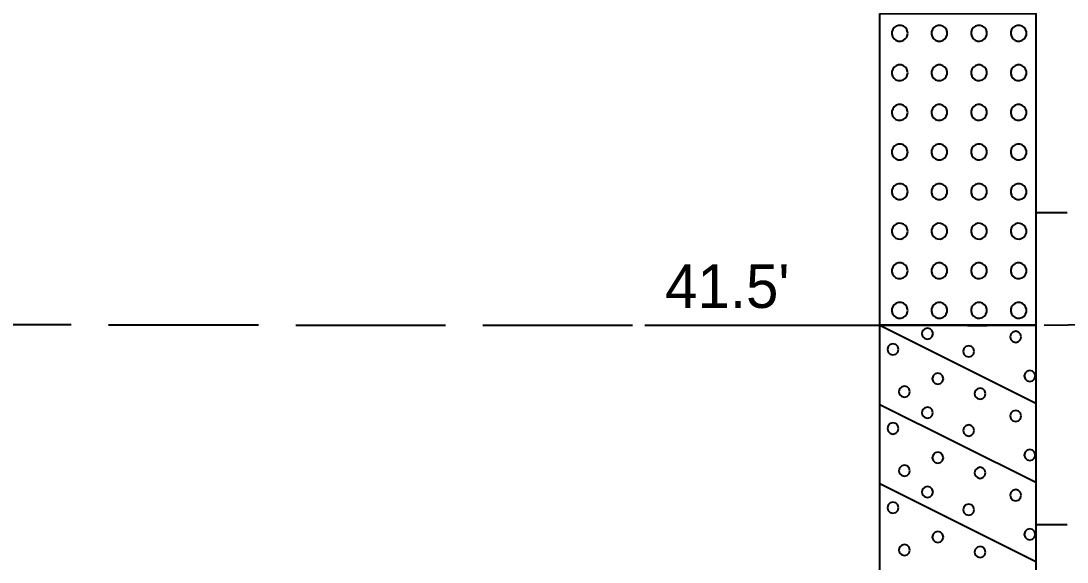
# Model space of a CAD drawing. Extents: x -582 to 653, y -817 to -3.
# Drawn here: x -81.59 to -64.82, y -739.22 to -730.54 of the extents above; entities that cross this region are included whole.
import ezdxf

# ---------------------------------------------------------------- set-up
doc = ezdxf.new("R2010")
doc.units = 0
doc.header["$LTSCALE"] = 0.4
doc.linetypes.add('LONG_DASHED', pattern=[7.5, 6, -1.5])
doc.layers.add('26', color=7, linetype='LONG_DASHED', lineweight=40)
doc.layers.add('27', color=7, linetype='Continuous', lineweight=40)

msp = doc.modelspace()

# ---------------------------------------------------------------- linework, layer by layer
at = {"layer": '26'}
msp.add_spline([(-89.1835, -735.3917), (-71.5863, -735.4226), (-67.8189, -735.4226), (-65.3189, -735.4226), (-45.0863, -734.6526), (-41.3189, -734.6526), (-38.8189, -734.6526), (-12.827, -734.6889)], degree=3, dxfattribs=at)
at = {"layer": '27'}
for p, q in [((-64.8189, -733.6226), (-65.3189, -733.6226)), ((-71.5863, -735.4226), (-67.8189, -735.4226)), ((-67.8189, -735.4226), (-65.3189, -736.6726)), ((-67.8189, -736.6926), (-65.3189, -737.9426)), ((-67.8189, -737.9626), (-65.3189, -739.2126)), ((-64.8189, -738.6226), (-65.3189, -738.6226))]:
    msp.add_line(p, q, dxfattribs=at)
for points in [[(-67.8189, -730.4226), (-65.3189, -730.4226), (-65.3189, -735.4226), (-67.8189, -735.4226)], [(-67.3743, -730.7401), (-67.3758, -730.7204), (-67.388, -730.6827), (-67.4111, -730.6506), (-67.443, -730.6272), (-67.4805, -730.6147), (-67.5201, -730.6144), (-67.5578, -730.6262), (-67.5901, -730.6491), (-67.6138, -730.6808), (-67.6266, -730.7182), (-67.6273, -730.7577), (-67.6158, -730.7956), (-67.5932, -730.8281), (-67.5618, -730.852), (-67.5245, -730.8652), (-67.4849, -730.8662), (-67.447, -730.855), (-67.4143, -730.8327), (-67.39, -730.8015), (-67.3766, -730.7643)], [(-66.7393, -730.7401), (-66.7408, -730.7204), (-66.753, -730.6827), (-66.7761, -730.6506), (-66.808, -730.6272), (-66.8455, -730.6147), (-66.8851, -730.6144), (-66.9228, -730.6262), (-66.9551, -730.6491), (-66.9788, -730.6808), (-66.9916, -730.7182), (-66.9923, -730.7577), (-66.9808, -730.7956), (-66.9582, -730.8281), (-66.9268, -730.852), (-66.8895, -730.8652), (-66.8499, -730.8662), (-66.812, -730.855), (-66.7793, -730.8327), (-66.755, -730.8015), (-66.7416, -730.7643)], [(-66.1043, -730.7401), (-66.1058, -730.7204), (-66.118, -730.6827), (-66.1411, -730.6506), (-66.173, -730.6272), (-66.2105, -730.6147), (-66.2501, -730.6144), (-66.2878, -730.6262), (-66.3201, -730.6491), (-66.3438, -730.6808), (-66.3566, -730.7182), (-66.3573, -730.7577), (-66.3458, -730.7956), (-66.3232, -730.8281), (-66.2918, -730.852), (-66.2545, -730.8652), (-66.2149, -730.8662), (-66.177, -730.855), (-66.1443, -730.8327), (-66.12, -730.8015), (-66.1066, -730.7643)], [(-65.4693, -730.7401), (-65.4708, -730.7204), (-65.483, -730.6827), (-65.5061, -730.6506), (-65.538, -730.6272), (-65.5755, -730.6147), (-65.6151, -730.6144), (-65.6528, -730.6262), (-65.6851, -730.6491), (-65.7088, -730.6808), (-65.7216, -730.7182), (-65.7223, -730.7577), (-65.7108, -730.7956), (-65.6882, -730.8281), (-65.6568, -730.852), (-65.6195, -730.8652), (-65.5799, -730.8662), (-65.542, -730.855), (-65.5093, -730.8327), (-65.485, -730.8015), (-65.4716, -730.7643)], [(-67.3743, -731.3751), (-67.3758, -731.3554), (-67.388, -731.3177), (-67.4111, -731.2856), (-67.443, -731.2622), (-67.4805, -731.2497), (-67.5201, -731.2494), (-67.5578, -731.2612), (-67.5901, -731.2841), (-67.6138, -731.3158), (-67.6266, -731.3532), (-67.6273, -731.3927), (-67.6158, -731.4306), (-67.5932, -731.4631), (-67.5618, -731.487), (-67.5245, -731.5002), (-67.4849, -731.5012), (-67.447, -731.49), (-67.4143, -731.4677), (-67.39, -731.4365), (-67.3766, -731.3993)], [(-66.7393, -731.3751), (-66.7408, -731.3554), (-66.753, -731.3177), (-66.7761, -731.2856), (-66.808, -731.2622), (-66.8455, -731.2497), (-66.8851, -731.2494), (-66.9228, -731.2612), (-66.9551, -731.2841), (-66.9788, -731.3158), (-66.9916, -731.3532), (-66.9923, -731.3927), (-66.9808, -731.4306), (-66.9582, -731.4631), (-66.9268, -731.487), (-66.8895, -731.5002), (-66.8499, -731.5012), (-66.812, -731.49), (-66.7793, -731.4677), (-66.755, -731.4365), (-66.7416, -731.3993)], [(-66.1043, -731.3751), (-66.1058, -731.3554), (-66.118, -731.3177), (-66.1411, -731.2856), (-66.173, -731.2622), (-66.2105, -731.2497), (-66.2501, -731.2494), (-66.2878, -731.2612), (-66.3201, -731.2841), (-66.3438, -731.3158), (-66.3566, -731.3532), (-66.3573, -731.3927), (-66.3458, -731.4306), (-66.3232, -731.4631), (-66.2918, -731.487), (-66.2545, -731.5002), (-66.2149, -731.5012), (-66.177, -731.49), (-66.1443, -731.4677), (-66.12, -731.4365), (-66.1066, -731.3993)], [(-65.4693, -731.3751), (-65.4708, -731.3554), (-65.483, -731.3177), (-65.5061, -731.2856), (-65.538, -731.2622), (-65.5755, -731.2497), (-65.6151, -731.2494), (-65.6528, -731.2612), (-65.6851, -731.2841), (-65.7088, -731.3158), (-65.7216, -731.3532), (-65.7223, -731.3927), (-65.7108, -731.4306), (-65.6882, -731.4631), (-65.6568, -731.487), (-65.6195, -731.5002), (-65.5799, -731.5012), (-65.542, -731.49), (-65.5093, -731.4677), (-65.485, -731.4365), (-65.4716, -731.3993)], [(-67.3743, -732.0101), (-67.3758, -731.9904), (-67.388, -731.9527), (-67.4111, -731.9206), (-67.443, -731.8972), (-67.4805, -731.8847), (-67.5201, -731.8844), (-67.5578, -731.8962), (-67.5901, -731.9191), (-67.6138, -731.9508), (-67.6266, -731.9882), (-67.6273, -732.0277), (-67.6158, -732.0656), (-67.5932, -732.0981), (-67.5618, -732.122), (-67.5245, -732.1352), (-67.4849, -732.1362), (-67.447, -732.125), (-67.4143, -732.1027), (-67.39, -732.0715), (-67.3766, -732.0343)], [(-66.7393, -732.0101), (-66.7408, -731.9904), (-66.753, -731.9527), (-66.7761, -731.9206), (-66.808, -731.8972), (-66.8455, -731.8847), (-66.8851, -731.8844), (-66.9228, -731.8962), (-66.9551, -731.9191), (-66.9788, -731.9508), (-66.9916, -731.9882), (-66.9923, -732.0277), (-66.9808, -732.0656), (-66.9582, -732.0981), (-66.9268, -732.122), (-66.8895, -732.1352), (-66.8499, -732.1362), (-66.812, -732.125), (-66.7793, -732.1027), (-66.755, -732.0715), (-66.7416, -732.0343)], [(-66.1043, -732.0101), (-66.1058, -731.9904), (-66.118, -731.9527), (-66.1411, -731.9206), (-66.173, -731.8972), (-66.2105, -731.8847), (-66.2501, -731.8844), (-66.2878, -731.8962), (-66.3201, -731.9191), (-66.3438, -731.9508), (-66.3566, -731.9882), (-66.3573, -732.0277), (-66.3458, -732.0656), (-66.3232, -732.0981), (-66.2918, -732.122), (-66.2545, -732.1352), (-66.2149, -732.1362), (-66.177, -732.125), (-66.1443, -732.1027), (-66.12, -732.0715), (-66.1066, -732.0343)], [(-65.4693, -732.0101), (-65.4708, -731.9904), (-65.483, -731.9527), (-65.5061, -731.9206), (-65.538, -731.8972), (-65.5755, -731.8847), (-65.6151, -731.8844), (-65.6528, -731.8962), (-65.6851, -731.9191), (-65.7088, -731.9508), (-65.7216, -731.9882), (-65.7223, -732.0277), (-65.7108, -732.0656), (-65.6882, -732.0981), (-65.6568, -732.122), (-65.6195, -732.1352), (-65.5799, -732.1362), (-65.542, -732.125), (-65.5093, -732.1027), (-65.485, -732.0715), (-65.4716, -732.0343)], [(-67.3743, -732.6451), (-67.3758, -732.6254), (-67.388, -732.5877), (-67.4111, -732.5556), (-67.443, -732.5322), (-67.4805, -732.5197), (-67.5201, -732.5194), (-67.5578, -732.5312), (-67.5901, -732.5541), (-67.6138, -732.5858), (-67.6266, -732.6232), (-67.6273, -732.6627), (-67.6158, -732.7006), (-67.5932, -732.7331), (-67.5618, -732.757), (-67.5245, -732.7702), (-67.4849, -732.7712), (-67.447, -732.76), (-67.4143, -732.7377), (-67.39, -732.7065), (-67.3766, -732.6693)], [(-66.7393, -732.6451), (-66.7408, -732.6254), (-66.753, -732.5877), (-66.7761, -732.5556), (-66.808, -732.5322), (-66.8455, -732.5197), (-66.8851, -732.5194), (-66.9228, -732.5312), (-66.9551, -732.5541), (-66.9788, -732.5858), (-66.9916, -732.6232), (-66.9923, -732.6627), (-66.9808, -732.7006), (-66.9582, -732.7331), (-66.9268, -732.757), (-66.8895, -732.7702), (-66.8499, -732.7712), (-66.812, -732.76), (-66.7793, -732.7377), (-66.755, -732.7065), (-66.7416, -732.6693)], [(-66.1043, -732.6451), (-66.1058, -732.6254), (-66.118, -732.5877), (-66.1411, -732.5556), (-66.173, -732.5322), (-66.2105, -732.5197), (-66.2501, -732.5194), (-66.2878, -732.5312), (-66.3201, -732.5541), (-66.3438, -732.5858), (-66.3566, -732.6232), (-66.3573, -732.6627), (-66.3458, -732.7006), (-66.3232, -732.7331), (-66.2918, -732.757), (-66.2545, -732.7702), (-66.2149, -732.7712), (-66.177, -732.76), (-66.1443, -732.7377), (-66.12, -732.7065), (-66.1066, -732.6693)], [(-65.4693, -732.6451), (-65.4708, -732.6254), (-65.483, -732.5877), (-65.5061, -732.5556), (-65.538, -732.5322), (-65.5755, -732.5197), (-65.6151, -732.5194), (-65.6528, -732.5312), (-65.6851, -732.5541), (-65.7088, -732.5858), (-65.7216, -732.6232), (-65.7223, -732.6627), (-65.7108, -732.7006), (-65.6882, -732.7331), (-65.6568, -732.757), (-65.6195, -732.7702), (-65.5799, -732.7712), (-65.542, -732.76), (-65.5093, -732.7377), (-65.485, -732.7065), (-65.4716, -732.6693)], [(-67.3743, -733.2801), (-67.3758, -733.2604), (-67.388, -733.2227), (-67.4111, -733.1906), (-67.443, -733.1672), (-67.4805, -733.1547), (-67.5201, -733.1544), (-67.5578, -733.1662), (-67.5901, -733.1891), (-67.6138, -733.2208), (-67.6266, -733.2582), (-67.6273, -733.2977), (-67.6158, -733.3356), (-67.5932, -733.3681), (-67.5618, -733.392), (-67.5245, -733.4052), (-67.4849, -733.4062), (-67.447, -733.395), (-67.4143, -733.3727), (-67.39, -733.3415), (-67.3766, -733.3043)], [(-66.7393, -733.2801), (-66.7408, -733.2604), (-66.753, -733.2227), (-66.7761, -733.1906), (-66.808, -733.1672), (-66.8455, -733.1547), (-66.8851, -733.1544), (-66.9228, -733.1662), (-66.9551, -733.1891), (-66.9788, -733.2208), (-66.9916, -733.2582), (-66.9923, -733.2977), (-66.9808, -733.3356), (-66.9582, -733.3681), (-66.9268, -733.392), (-66.8895, -733.4052), (-66.8499, -733.4062), (-66.812, -733.395), (-66.7793, -733.3727), (-66.755, -733.3415), (-66.7416, -733.3043)], [(-66.1043, -733.2801), (-66.1058, -733.2604), (-66.118, -733.2227), (-66.1411, -733.1906), (-66.173, -733.1672), (-66.2105, -733.1547), (-66.2501, -733.1544), (-66.2878, -733.1662), (-66.3201, -733.1891), (-66.3438, -733.2208), (-66.3566, -733.2582), (-66.3573, -733.2977), (-66.3458, -733.3356), (-66.3232, -733.3681), (-66.2918, -733.392), (-66.2545, -733.4052), (-66.2149, -733.4062), (-66.177, -733.395), (-66.1443, -733.3727), (-66.12, -733.3415), (-66.1066, -733.3043)], [(-65.4693, -733.2801), (-65.4708, -733.2604), (-65.483, -733.2227), (-65.5061, -733.1906), (-65.538, -733.1672), (-65.5755, -733.1547), (-65.6151, -733.1544), (-65.6528, -733.1662), (-65.6851, -733.1891), (-65.7088, -733.2208), (-65.7216, -733.2582), (-65.7223, -733.2977), (-65.7108, -733.3356), (-65.6882, -733.3681), (-65.6568, -733.392), (-65.6195, -733.4052), (-65.5799, -733.4062), (-65.542, -733.395), (-65.5093, -733.3727), (-65.485, -733.3415), (-65.4716, -733.3043)], [(-67.3743, -733.9151), (-67.3758, -733.8954), (-67.388, -733.8577), (-67.4111, -733.8256), (-67.443, -733.8022), (-67.4805, -733.7897), (-67.5201, -733.7894), (-67.5578, -733.8012), (-67.5901, -733.8241), (-67.6138, -733.8558), (-67.6266, -733.8932), (-67.6273, -733.9327), (-67.6158, -733.9706), (-67.5932, -734.0031), (-67.5618, -734.027), (-67.5245, -734.0402), (-67.4849, -734.0412), (-67.447, -734.03), (-67.4143, -734.0077), (-67.39, -733.9765), (-67.3766, -733.9393)], [(-66.7393, -733.9151), (-66.7408, -733.8954), (-66.753, -733.8577), (-66.7761, -733.8256), (-66.808, -733.8022), (-66.8455, -733.7897), (-66.8851, -733.7894), (-66.9228, -733.8012), (-66.9551, -733.8241), (-66.9788, -733.8558), (-66.9916, -733.8932), (-66.9923, -733.9327), (-66.9808, -733.9706), (-66.9582, -734.0031), (-66.9268, -734.027), (-66.8895, -734.0402), (-66.8499, -734.0412), (-66.812, -734.03), (-66.7793, -734.0077), (-66.755, -733.9765), (-66.7416, -733.9393)], [(-66.1043, -733.9151), (-66.1058, -733.8954), (-66.118, -733.8577), (-66.1411, -733.8256), (-66.173, -733.8022), (-66.2105, -733.7897), (-66.2501, -733.7894), (-66.2878, -733.8012), (-66.3201, -733.8241), (-66.3438, -733.8558), (-66.3566, -733.8932), (-66.3573, -733.9327), (-66.3458, -733.9706), (-66.3232, -734.0031), (-66.2918, -734.027), (-66.2545, -734.0402), (-66.2149, -734.0412), (-66.177, -734.03), (-66.1443, -734.0077), (-66.12, -733.9765), (-66.1066, -733.9393)], [(-65.4693, -733.9151), (-65.4708, -733.8954), (-65.483, -733.8577), (-65.5061, -733.8256), (-65.538, -733.8022), (-65.5755, -733.7897), (-65.6151, -733.7894), (-65.6528, -733.8012), (-65.6851, -733.8241), (-65.7088, -733.8558), (-65.7216, -733.8932), (-65.7223, -733.9327), (-65.7108, -733.9706), (-65.6882, -734.0031), (-65.6568, -734.027), (-65.6195, -734.0402), (-65.5799, -734.0412), (-65.542, -734.03), (-65.5093, -734.0077), (-65.485, -733.9765), (-65.4716, -733.9393)], [(-67.3743, -734.5501), (-67.3758, -734.5304), (-67.388, -734.4927), (-67.4111, -734.4606), (-67.443, -734.4372), (-67.4805, -734.4247), (-67.5201, -734.4244), (-67.5578, -734.4362), (-67.5901, -734.4591), (-67.6138, -734.4908), (-67.6266, -734.5282), (-67.6273, -734.5677), (-67.6158, -734.6056), (-67.5932, -734.6381), (-67.5618, -734.662), (-67.5245, -734.6752), (-67.4849, -734.6762), (-67.447, -734.665), (-67.4143, -734.6427), (-67.39, -734.6115), (-67.3766, -734.5743)], [(-66.7393, -734.5501), (-66.7408, -734.5304), (-66.753, -734.4927), (-66.7761, -734.4606), (-66.808, -734.4372), (-66.8455, -734.4247), (-66.8851, -734.4244), (-66.9228, -734.4362), (-66.9551, -734.4591), (-66.9788, -734.4908), (-66.9916, -734.5282), (-66.9923, -734.5677), (-66.9808, -734.6056), (-66.9582, -734.6381), (-66.9268, -734.662), (-66.8895, -734.6752), (-66.8499, -734.6762), (-66.812, -734.665), (-66.7793, -734.6427), (-66.755, -734.6115), (-66.7416, -734.5743)], [(-66.1043, -734.5501), (-66.1058, -734.5304), (-66.118, -734.4927), (-66.1411, -734.4606), (-66.173, -734.4372), (-66.2105, -734.4247), (-66.2501, -734.4244), (-66.2878, -734.4362), (-66.3201, -734.4591), (-66.3438, -734.4908), (-66.3566, -734.5282), (-66.3573, -734.5677), (-66.3458, -734.6056), (-66.3232, -734.6381), (-66.2918, -734.662), (-66.2545, -734.6752), (-66.2149, -734.6762), (-66.177, -734.665), (-66.1443, -734.6427), (-66.12, -734.6115), (-66.1066, -734.5743)], [(-65.4693, -734.5501), (-65.4708, -734.5304), (-65.483, -734.4927), (-65.5061, -734.4606), (-65.538, -734.4372), (-65.5755, -734.4247), (-65.6151, -734.4244), (-65.6528, -734.4362), (-65.6851, -734.4591), (-65.7088, -734.4908), (-65.7216, -734.5282), (-65.7223, -734.5677), (-65.7108, -734.6056), (-65.6882, -734.6381), (-65.6568, -734.662), (-65.6195, -734.6752), (-65.5799, -734.6762), (-65.542, -734.665), (-65.5093, -734.6427), (-65.485, -734.6115), (-65.4716, -734.5743)], [(-67.3743, -735.1851), (-67.3758, -735.1654), (-67.388, -735.1277), (-67.4111, -735.0956), (-67.443, -735.0722), (-67.4805, -735.0597), (-67.5201, -735.0594), (-67.5578, -735.0712), (-67.5901, -735.0941), (-67.6138, -735.1258), (-67.6266, -735.1632), (-67.6273, -735.2027), (-67.6158, -735.2406), (-67.5932, -735.2731), (-67.5618, -735.297), (-67.5245, -735.3102), (-67.4849, -735.3112), (-67.447, -735.3), (-67.4143, -735.2777), (-67.39, -735.2465), (-67.3766, -735.2093)], [(-66.7393, -735.1851), (-66.7408, -735.1654), (-66.753, -735.1277), (-66.7761, -735.0956), (-66.808, -735.0722), (-66.8455, -735.0597), (-66.8851, -735.0594), (-66.9228, -735.0712), (-66.9551, -735.0941), (-66.9788, -735.1258), (-66.9916, -735.1632), (-66.9923, -735.2027), (-66.9808, -735.2406), (-66.9582, -735.2731), (-66.9268, -735.297), (-66.8895, -735.3102), (-66.8499, -735.3112), (-66.812, -735.3), (-66.7793, -735.2777), (-66.755, -735.2465), (-66.7416, -735.2093)], [(-66.1043, -735.1851), (-66.1058, -735.1654), (-66.118, -735.1277), (-66.1411, -735.0956), (-66.173, -735.0722), (-66.2105, -735.0597), (-66.2501, -735.0594), (-66.2878, -735.0712), (-66.3201, -735.0941), (-66.3438, -735.1258), (-66.3566, -735.1632), (-66.3573, -735.2027), (-66.3458, -735.2406), (-66.3232, -735.2731), (-66.2918, -735.297), (-66.2545, -735.3102), (-66.2149, -735.3112), (-66.177, -735.3), (-66.1443, -735.2777), (-66.12, -735.2465), (-66.1066, -735.2093)], [(-65.4693, -735.1851), (-65.4708, -735.1654), (-65.483, -735.1277), (-65.5061, -735.0956), (-65.538, -735.0722), (-65.5755, -735.0597), (-65.6151, -735.0594), (-65.6528, -735.0712), (-65.6851, -735.0941), (-65.7088, -735.1258), (-65.7216, -735.1632), (-65.7223, -735.2027), (-65.7108, -735.2406), (-65.6882, -735.2731), (-65.6568, -735.297), (-65.6195, -735.3102), (-65.5799, -735.3112), (-65.542, -735.3), (-65.5093, -735.2777), (-65.485, -735.2465), (-65.4716, -735.2093)], [(-67.8189, -735.4226), (-65.3189, -735.4226), (-65.3189, -740.4226), (-67.8189, -740.4226)], [(-66.9682, -735.5589), (-66.9801, -735.5145), (-67.0126, -735.482), (-67.0571, -735.47), (-67.1015, -735.482), (-67.1341, -735.5145), (-67.146, -735.5589), (-67.1341, -735.6034), (-67.1015, -735.6359), (-67.0571, -735.6478), (-67.0126, -735.6359), (-66.9801, -735.6034)], [(-65.5534, -735.6099), (-65.5653, -735.5654), (-65.5978, -735.5329), (-65.6423, -735.521), (-65.6867, -735.5329), (-65.7192, -735.5654), (-65.7312, -735.6099), (-65.7192, -735.6543), (-65.6867, -735.6869), (-65.6423, -735.6988), (-65.5978, -735.6869), (-65.5653, -735.6543)], [(-67.5213, -735.8107), (-67.5332, -735.7663), (-67.5657, -735.7337), (-67.6102, -735.7218), (-67.6546, -735.7337), (-67.6872, -735.7663), (-67.6991, -735.8107), (-67.6872, -735.8552), (-67.6546, -735.8877), (-67.6102, -735.8996), (-67.5657, -735.8877), (-67.5332, -735.8552)], [(-66.3059, -735.8438), (-66.3179, -735.7993), (-66.3504, -735.7668), (-66.3948, -735.7549), (-66.4393, -735.7668), (-66.4718, -735.7993), (-66.4837, -735.8438), (-66.4718, -735.8882), (-66.4393, -735.9208), (-66.3948, -735.9327), (-66.3504, -735.9208), (-66.3179, -735.8882)], [(-66.8017, -736.2811), (-66.8137, -736.2367), (-66.8462, -736.2041), (-66.8906, -736.1922), (-66.9351, -736.2041), (-66.9676, -736.2367), (-66.9795, -736.2811), (-66.9676, -736.3256), (-66.9351, -736.3581), (-66.8906, -736.37), (-66.8462, -736.3581), (-66.8137, -736.3256)], [(-65.3271, -736.2379), (-65.339, -736.1934), (-65.3715, -736.1609), (-65.416, -736.149), (-65.4604, -736.1609), (-65.493, -736.1934), (-65.5049, -736.2379), (-65.493, -736.2823), (-65.4604, -736.3149), (-65.416, -736.3268), (-65.3715, -736.3149), (-65.339, -736.2823)], [(-67.337, -736.4896), (-67.3489, -736.4451), (-67.3814, -736.4126), (-67.4259, -736.4007), (-67.4703, -736.4126), (-67.5028, -736.4451), (-67.5148, -736.4896), (-67.5028, -736.534), (-67.4703, -736.5666), (-67.4259, -736.5785), (-67.3814, -736.5666), (-67.3489, -736.534)], [(-66.1242, -736.5226), (-66.1361, -736.4782), (-66.1686, -736.4457), (-66.2131, -736.4337), (-66.2575, -736.4457), (-66.29, -736.4782), (-66.302, -736.5226), (-66.29, -736.5671), (-66.2575, -736.5996), (-66.2131, -736.6115), (-66.1686, -736.5996), (-66.1361, -736.5671)], [(-66.9683, -736.8278), (-66.9802, -736.7833), (-67.0127, -736.7508), (-67.0572, -736.7389), (-67.1016, -736.7508), (-67.1342, -736.7833), (-67.1461, -736.8278), (-67.1342, -736.8722), (-67.1016, -736.9047), (-67.0572, -736.9167), (-67.0127, -736.9047), (-66.9802, -736.8722)], [(-65.5534, -736.8786), (-65.5653, -736.8342), (-65.5978, -736.8016), (-65.6423, -736.7897), (-65.6867, -736.8016), (-65.7192, -736.8342), (-65.7312, -736.8786), (-65.7192, -736.9231), (-65.6867, -736.9556), (-65.6423, -736.9675), (-65.5978, -736.9556), (-65.5653, -736.9231)], [(-67.5213, -737.0795), (-67.5332, -737.035), (-67.5657, -737.0025), (-67.6102, -736.9906), (-67.6546, -737.0025), (-67.6872, -737.035), (-67.6991, -737.0795), (-67.6872, -737.1239), (-67.6546, -737.1565), (-67.6102, -737.1684), (-67.5657, -737.1565), (-67.5332, -737.1239)], [(-66.3059, -737.1125), (-66.3179, -737.0681), (-66.3504, -737.0355), (-66.3948, -737.0236), (-66.4393, -737.0355), (-66.4718, -737.0681), (-66.4837, -737.1125), (-66.4718, -737.157), (-66.4393, -737.1895), (-66.3948, -737.2014), (-66.3504, -737.1895), (-66.3179, -737.157)], [(-66.8017, -737.5498), (-66.8137, -737.5054), (-66.8462, -737.4728), (-66.8906, -737.4609), (-66.9351, -737.4728), (-66.9676, -737.5054), (-66.9795, -737.5498), (-66.9676, -737.5943), (-66.9351, -737.6268), (-66.8906, -737.6387), (-66.8462, -737.6268), (-66.8137, -737.5943)], [(-65.3271, -737.5066), (-65.339, -737.4622), (-65.3715, -737.4296), (-65.416, -737.4177), (-65.4604, -737.4296), (-65.493, -737.4622), (-65.5049, -737.5066), (-65.493, -737.5511), (-65.4604, -737.5836), (-65.416, -737.5955), (-65.3715, -737.5836), (-65.339, -737.5511)], [(-67.337, -737.7583), (-67.3489, -737.7139), (-67.3814, -737.6813), (-67.4259, -737.6694), (-67.4703, -737.6813), (-67.5028, -737.7139), (-67.5148, -737.7583), (-67.5028, -737.8028), (-67.4703, -737.8353), (-67.4259, -737.8472), (-67.3814, -737.8353), (-67.3489, -737.8028)], [(-66.1242, -737.7914), (-66.1361, -737.7469), (-66.1686, -737.7144), (-66.2131, -737.7025), (-66.2575, -737.7144), (-66.29, -737.7469), (-66.302, -737.7914), (-66.29, -737.8358), (-66.2575, -737.8684), (-66.2131, -737.8803), (-66.1686, -737.8684), (-66.1361, -737.8358)], [(-66.9682, -738.0989), (-66.9801, -738.0545), (-67.0126, -738.022), (-67.0571, -738.01), (-67.1015, -738.022), (-67.1341, -738.0545), (-67.146, -738.0989), (-67.1341, -738.1434), (-67.1015, -738.1759), (-67.0571, -738.1878), (-67.0126, -738.1759), (-66.9801, -738.1434)], [(-65.5534, -738.1499), (-65.5653, -738.1054), (-65.5978, -738.0729), (-65.6423, -738.061), (-65.6867, -738.0729), (-65.7192, -738.1054), (-65.7312, -738.1499), (-65.7192, -738.1943), (-65.6867, -738.2269), (-65.6423, -738.2388), (-65.5978, -738.2269), (-65.5653, -738.1943)], [(-67.5213, -738.3507), (-67.5332, -738.3063), (-67.5657, -738.2737), (-67.6102, -738.2618), (-67.6546, -738.2737), (-67.6872, -738.3063), (-67.6991, -738.3507), (-67.6872, -738.3952), (-67.6546, -738.4277), (-67.6102, -738.4396), (-67.5657, -738.4277), (-67.5332, -738.3952)], [(-66.3059, -738.3838), (-66.3179, -738.3393), (-66.3504, -738.3068), (-66.3948, -738.2949), (-66.4393, -738.3068), (-66.4718, -738.3393), (-66.4837, -738.3838), (-66.4718, -738.4282), (-66.4393, -738.4608), (-66.3948, -738.4727), (-66.3504, -738.4608), (-66.3179, -738.4282)], [(-66.8017, -738.8211), (-66.8137, -738.7767), (-66.8462, -738.7441), (-66.8906, -738.7322), (-66.9351, -738.7441), (-66.9676, -738.7767), (-66.9795, -738.8211), (-66.9676, -738.8656), (-66.9351, -738.8981), (-66.8906, -738.91), (-66.8462, -738.8981), (-66.8137, -738.8656)], [(-65.3271, -738.7779), (-65.339, -738.7334), (-65.3715, -738.7009), (-65.416, -738.689), (-65.4604, -738.7009), (-65.493, -738.7334), (-65.5049, -738.7779), (-65.493, -738.8223), (-65.4604, -738.8549), (-65.416, -738.8668), (-65.3715, -738.8549), (-65.339, -738.8223)], [(-67.337, -739.0296), (-67.3489, -738.9851), (-67.3814, -738.9526), (-67.4259, -738.9407), (-67.4703, -738.9526), (-67.5028, -738.9851), (-67.5148, -739.0296), (-67.5028, -739.074), (-67.4703, -739.1066), (-67.4259, -739.1185), (-67.3814, -739.1066), (-67.3489, -739.074)], [(-66.1242, -739.0626), (-66.1361, -739.0182), (-66.1686, -738.9857), (-66.2131, -738.9737), (-66.2575, -738.9857), (-66.29, -739.0182), (-66.302, -739.0626), (-66.29, -739.1071), (-66.2575, -739.1396), (-66.2131, -739.1515), (-66.1686, -739.1396), (-66.1361, -739.1071)]]:
    msp.add_lwpolyline(points, close=True, dxfattribs=at)

# ---------------------------------------------------------------- texts
msp.add_text("41.5'", height=0.6976, dxfattribs=at).set_placement((-71.2623, -735.1461))

doc.saveas('drawing.dxf')
